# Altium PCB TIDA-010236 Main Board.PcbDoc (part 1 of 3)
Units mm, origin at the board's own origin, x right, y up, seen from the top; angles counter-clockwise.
Board outline 180 x 120 mm, 2 copper layers (Top Layer, Bottom Layer), stack 1.571 mm thick; 265 components, 145 nets, 704 pads, 547 vias.
Unrouted connection lines stored in the file: 155.
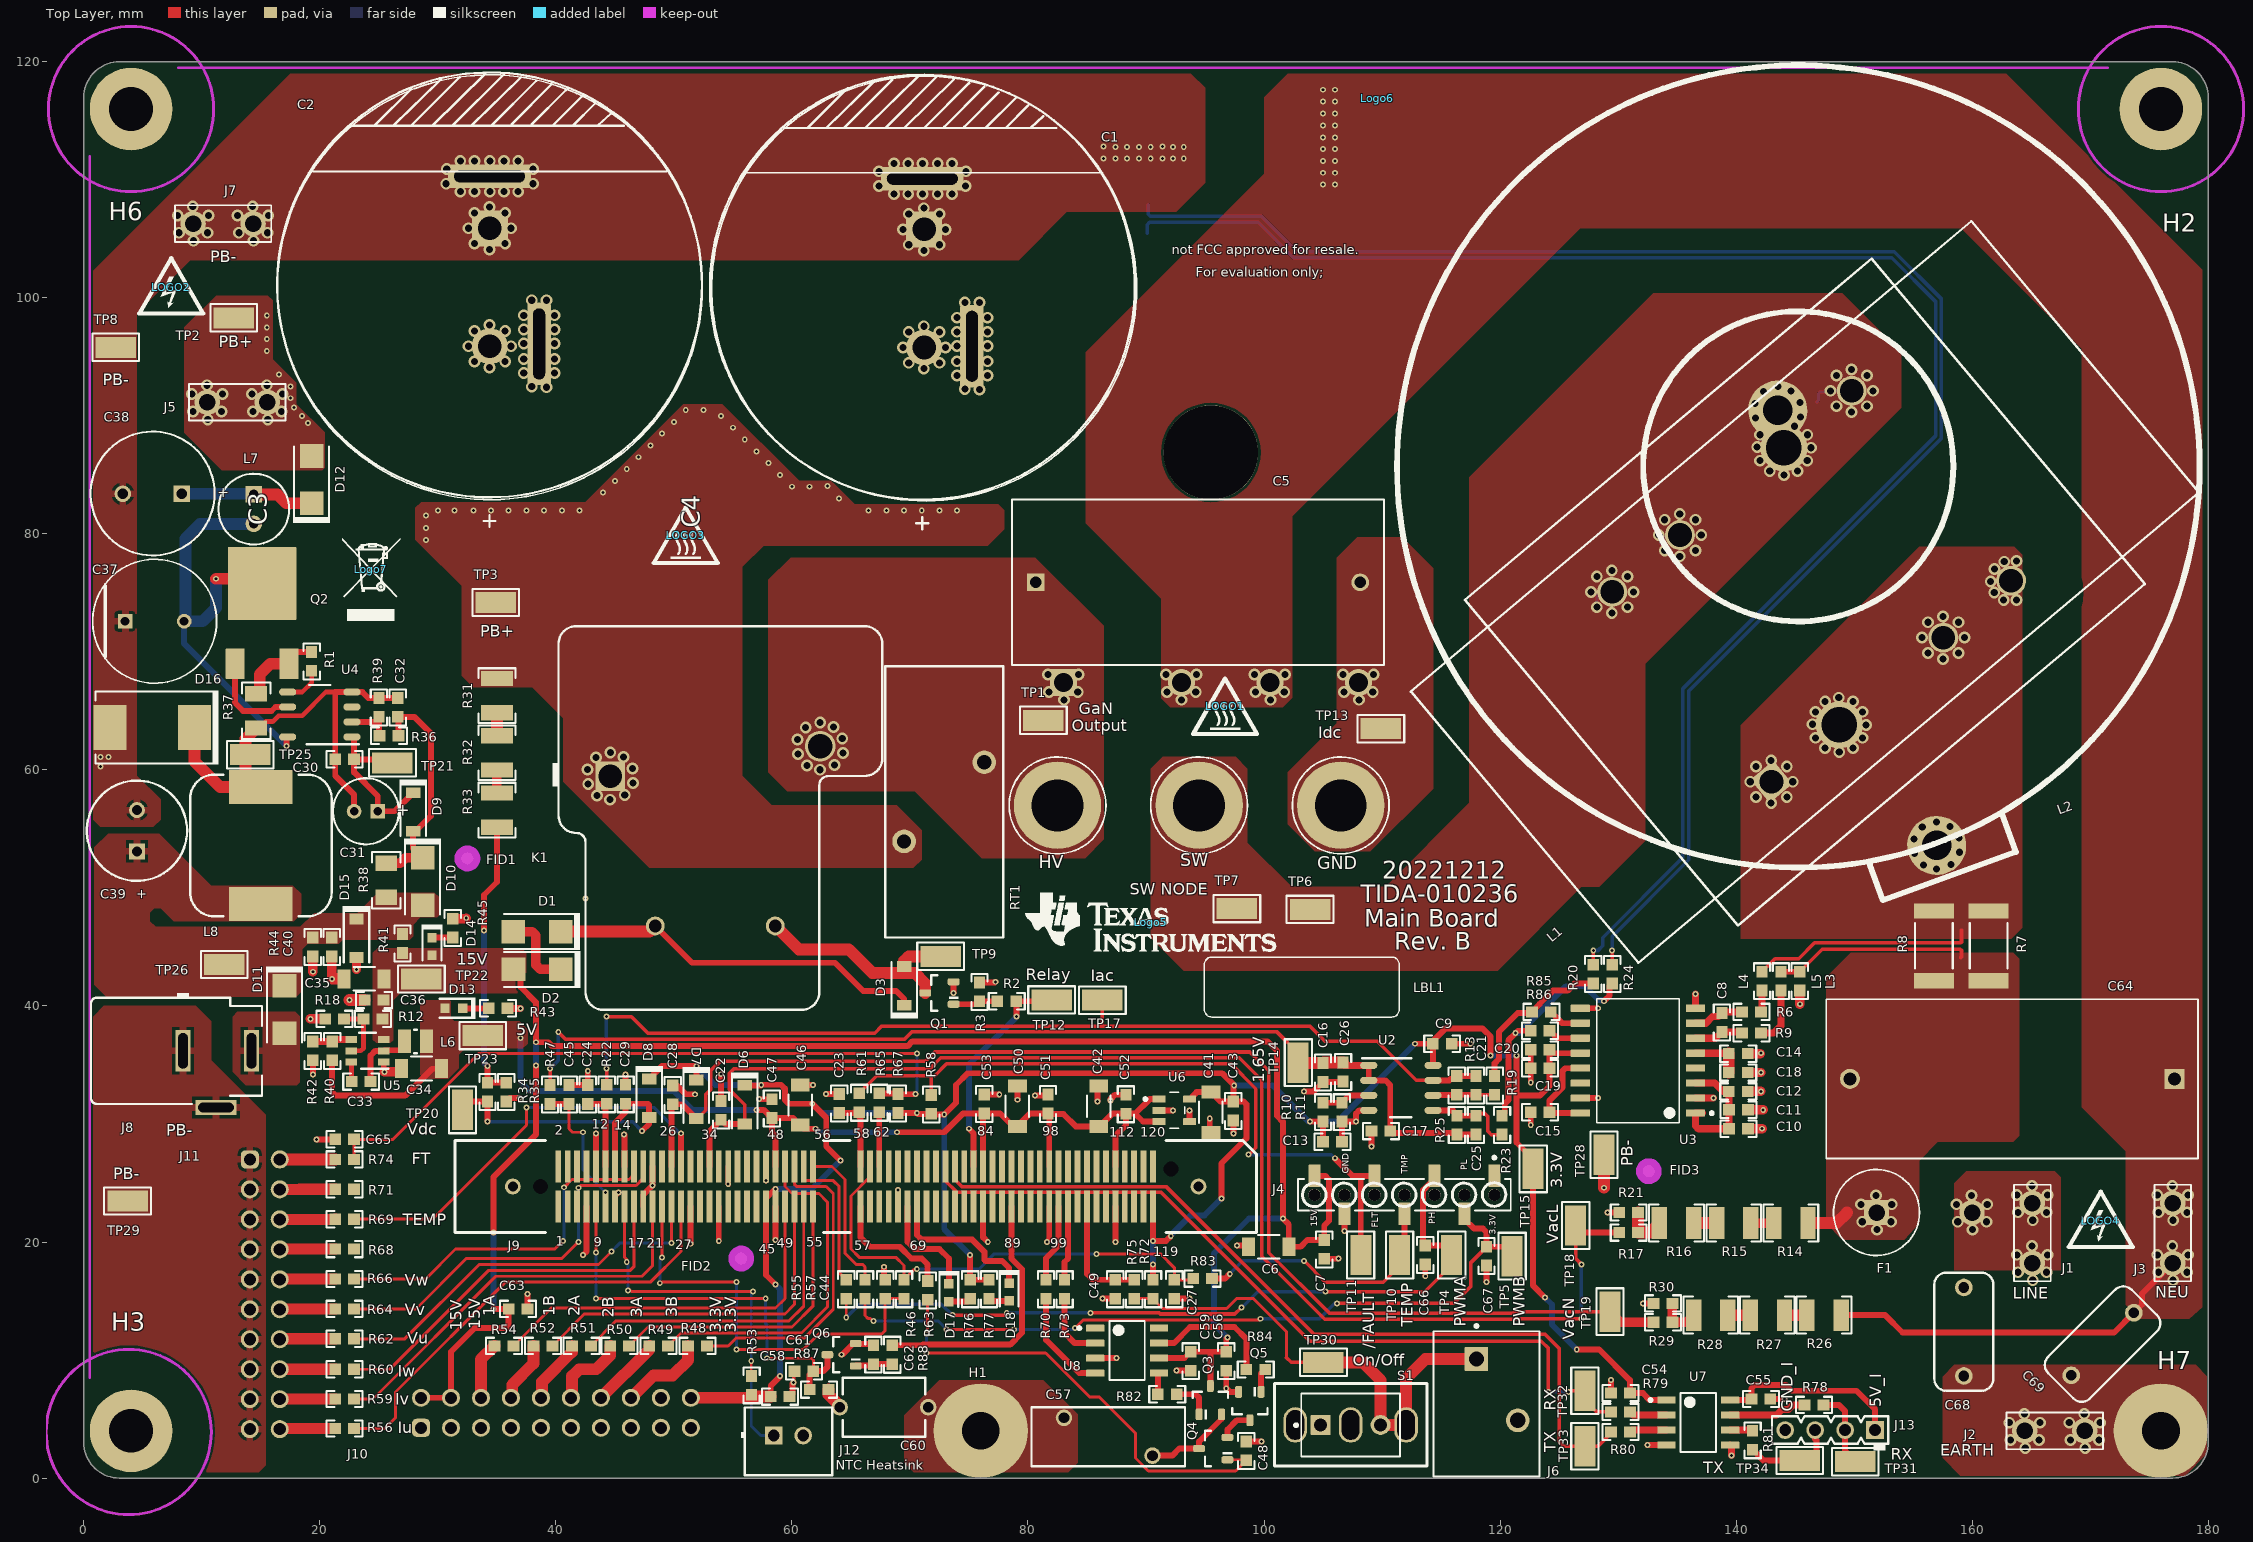
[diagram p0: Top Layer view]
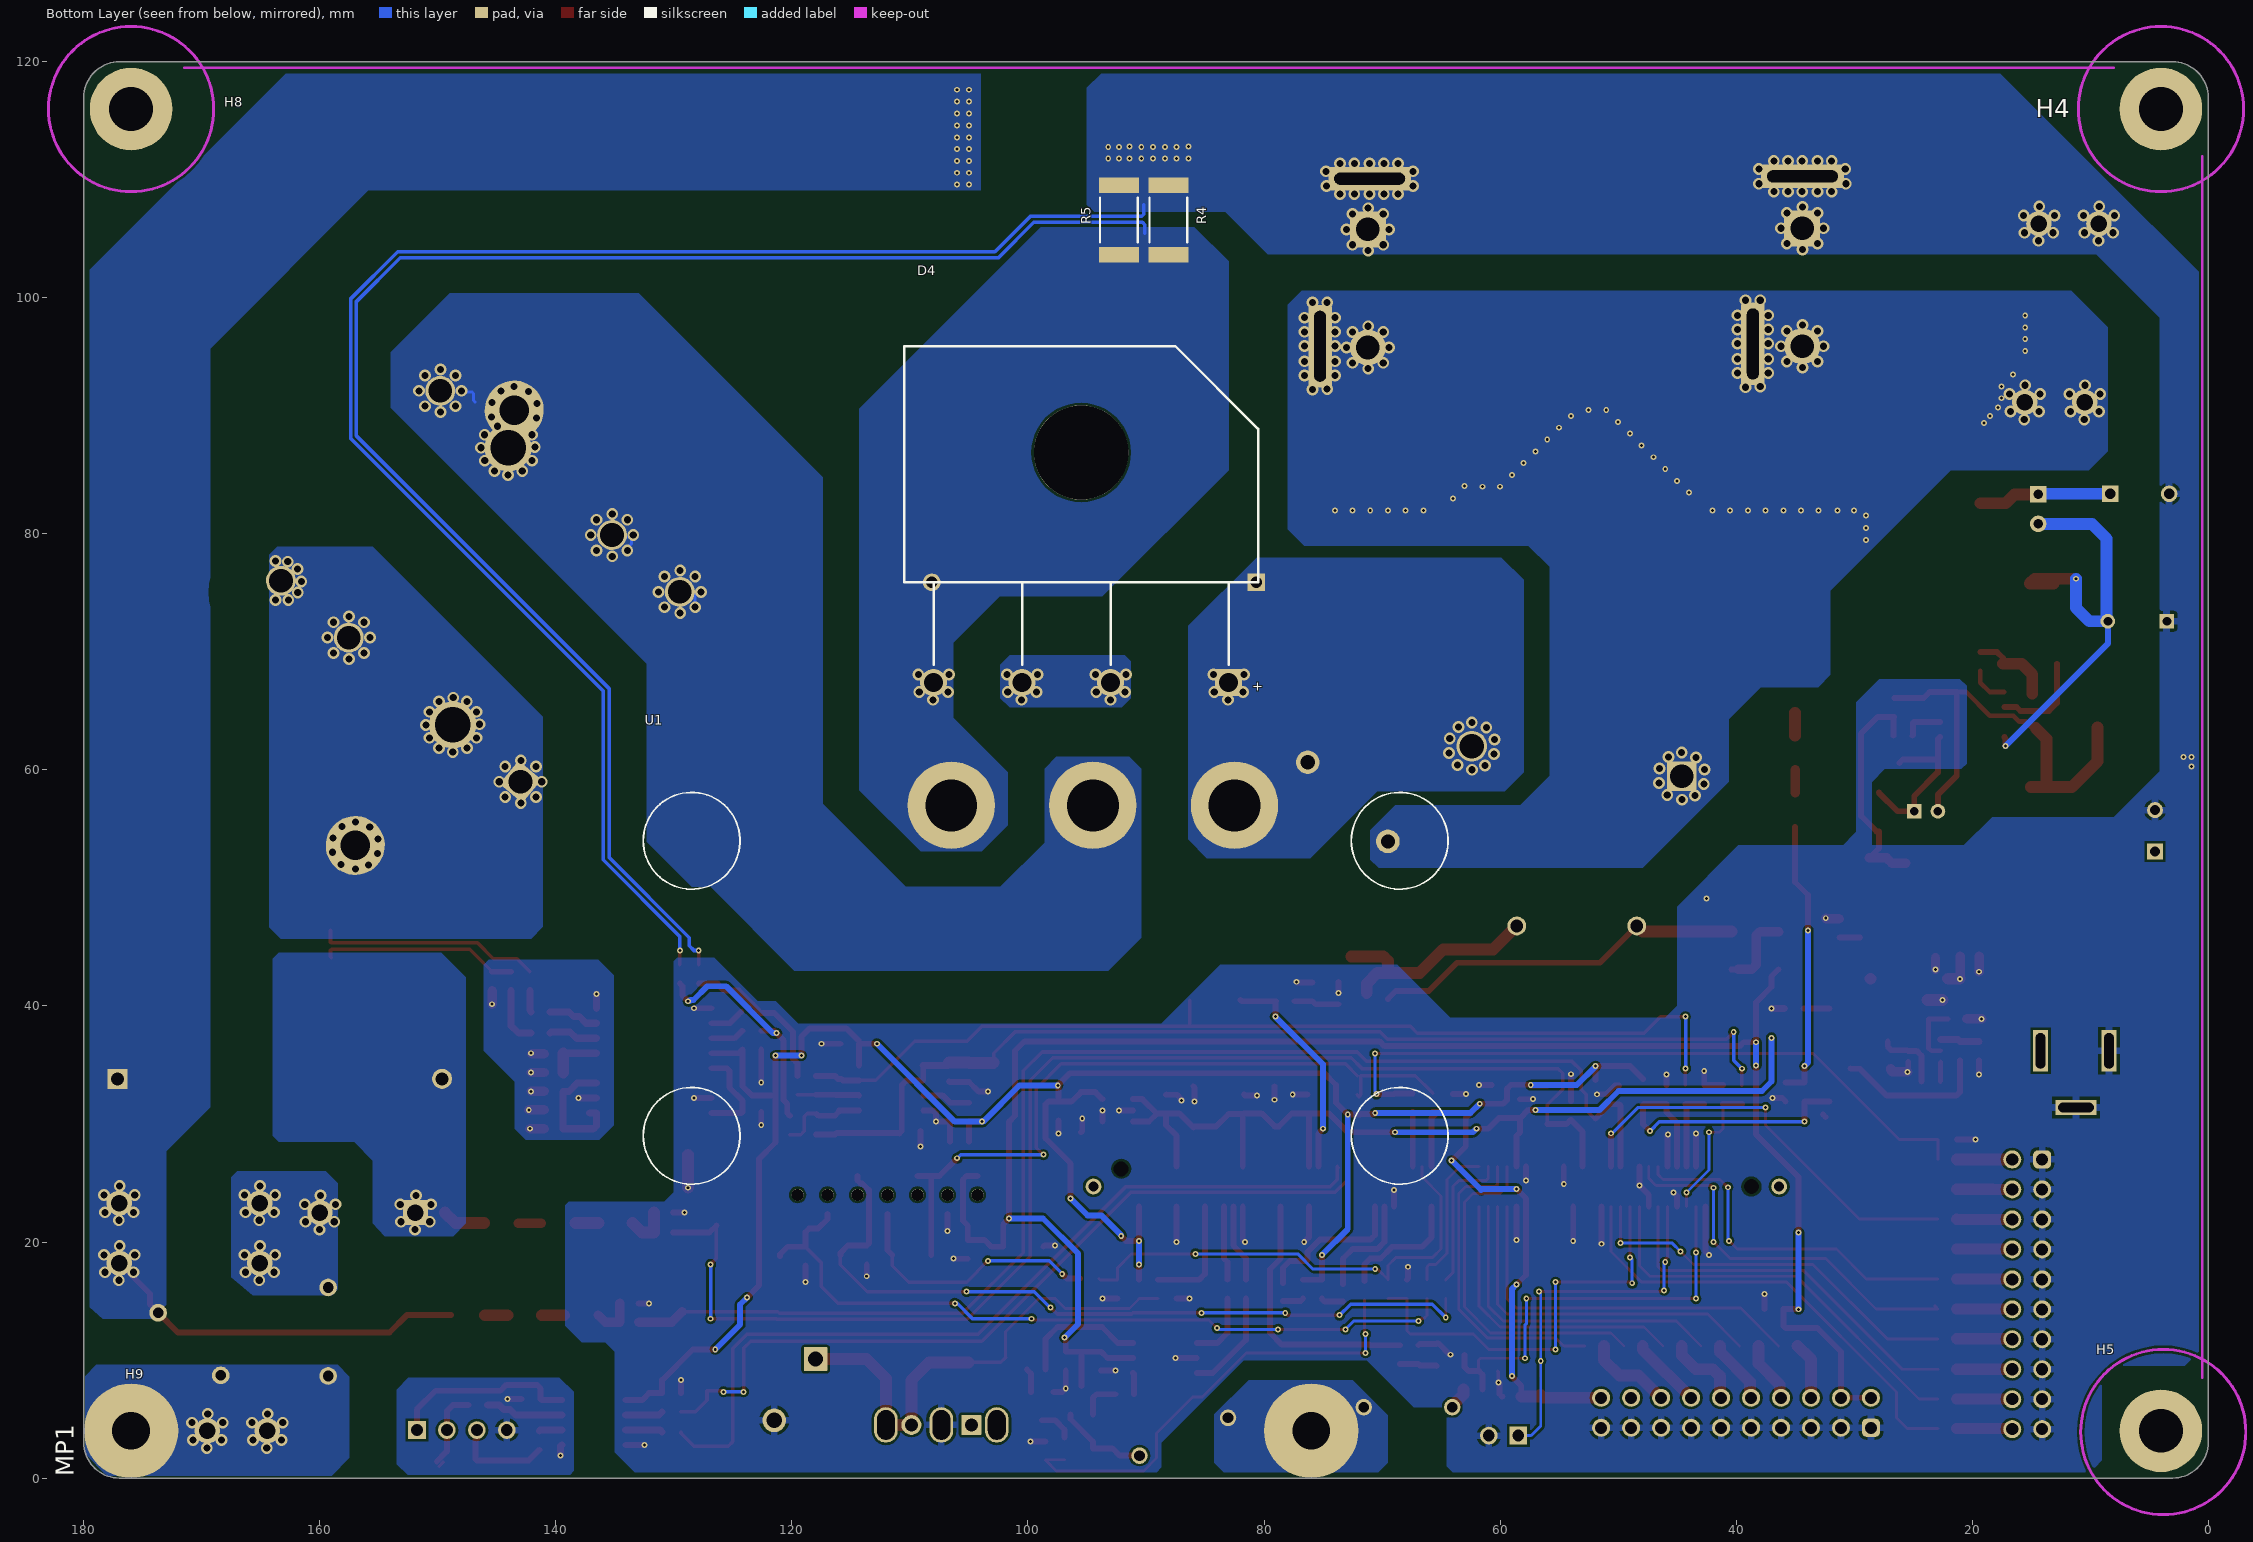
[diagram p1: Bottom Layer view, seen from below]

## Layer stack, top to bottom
Top Solder: solder mask 0.0102, Solder Resist, Dk 3.5
Top Layer: signal copper 0.0356
Dielectric 1: core 1.5, FR-4, Dk 4.2
Bottom Layer: signal copper 0.0356
Bottom Solder: solder mask 0.0102, Solder Resist, Dk 3.5

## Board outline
177,120 cw(c177,117) 180,117 180,3 cw(c177,3) 177,0 3,0 cw(c3,3) 0,3 0,117 cw(c3,117) 3,120

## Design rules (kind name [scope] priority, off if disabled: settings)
Clearance PB-ToACN [InNetClass('GND_NetClass') vs InNetClass('ACN_NetClass')] p1: gap=3 ignorepadtopadclearanceinfootprint=TRUE
Clearance ISOToAll [InNetClass('ISO_NetClass') vs Not (ISO_NetClass)] p2: gap=6.3 ignorepadtopadclearanceinfootprint=TRUE
Clearance PB-ToACL [InNetClass('GND_NetClass') vs InNetClass('ACL_NetClass')] p3: gap=2 ignorepadtopadclearanceinfootprint=TRUE
Clearance PB+ToACN [InNetClass('PB+_NetClass') vs InNetClass('ACN_NetClass')] p4: gap=3 ignorepadtopadclearanceinfootprint=FALSE
Clearance PB+ToACL [InNetClass('PB+_NetClass') vs InNetClass('ACL_NetClass')] p5: gap=3 ignorepadtopadclearanceinfootprint=TRUE
Clearance PB+ToPB- [InNetClass('PB+_NetClass') vs InNetClass('GND_NetClass')] p6: gap=1 ignorepadtopadclearanceinfootprint=TRUE
Clearance ACLToACN [InNetClass('ACL_NetClass') vs InNetClass('ACN_NetClass')] p7: gap=5 ignorepadtopadclearanceinfootprint=TRUE
Clearance SMTPadToTHHole [OnLayer('Multi-Layer') vs OnLayer('Bottom Paste')] p8: gap=0.35 ignorepadtopadclearanceinfootprint=FALSE except(0: Arc-Hole Track-Hole SMDPad-Hole THPad-Hole Via-Hole Fill-Hole Poly-Hole Region-Hole Text-Hole; 3: SMDPad-THPad)
Clearance [All] p9: gap=0.2 ignorepadtopadclearanceinfootprint=FALSE
ComponentClearance [All] p1 off: gap=0.254 collisioncheckmode=3 verticalgap=0.254 showdistances=FALSE
DiffPairsRouting DiffPair_CurrentDiffPairsRouting [InDifferentialPair('I')] p1: maxlimit=0.4 minlimit=0.2 mostfreqgap=0.25 toplayer_minwidth=0.2 toplayer_maxwidth=0.4 toplayer_prefwidth=0.25 bottomlayer_minwidth=0.2 bottomlayer_maxwidth=0.4 bottomlayer_prefwidth=0.25 maxuncoupledlength=12.7
FabricationTestPointUsage TestPointUsage [InNet('+5V')] p1: valid=0 allowmultiple=FALSE
FabricationTestpoint Testpoint [InNet('+5V')] p1: side=2 testpointundercomponent=TRUE minsize=0.4 maxsize=1 preferedsize=0.4 minholesize=0 maxholesize=1.016 preferedholesize=0.813 testpointgrid=0.025 allowsidebottom=TRUE usegrid=TRUE gridtolerance=0
Height [All] p1: minheight=0 maxheight=100 prefheight=12.7
HoleSize [All] p1: absolutevalues=TRUE maxlimit=10 minlimit=0.025 maxpercent=80.000 minpercent=20.000
MatchedLengths DiffPair_CurrentMatchedLengths [InDifferentialPair ('C')] p1: tolerance=25.4 checknetsindiffpair=FALSE checkdiffpairvsdiffpair=TRUE checkxsignals=TRUE checkothers=TRUE
MinimumSolderMaskSliver [All vs not InComponent('J9')] p1: minsoldermaskwidth=0.14
PlaneConnect [All] p1: planeconnectstyle=Direct reliefexpansion=0.508 reliefentries=4 reliefconductorwidth=0.254 reliefairgap=0.254
PolygonConnect Polygon_Direct [InComponent('U1') or InNet('NetD4_2')  or   InNet('EARTH')   OR InNet('EARTH1') or  InNet('LINE_Filtered')   or  InNet('LINE_Filtered1')   or  InNet('NEU_Filtered')   or  InNet('PBGan')    or  InNet('Idc') or  InNet('PB+')  or InComponent('L2')  or InComponent('C1') or InComponent('C2') or InComponent('C3')    or InComponent('C4')        or InComponent('J7')    or InComponent('L1')      or InComponent('F1')] p1: connectstyle=Direct reliefconductorwidth=0.254 reliefentries=4 polygonreliefangle="90 Angle" airgapwidth=0.254
PolygonConnect [All] p2: thpad.connectstyle=Relief thpad.reliefconductorwidth=0.6 thpad.reliefentries=4 thpad.polygonreliefangle="90 Angle" thpad.airgapwidth=0.254 smdpad.connectstyle=Direct smdpad.reliefconductorwidth=0.254 smdpad.reliefentries=4 smdpad.polygonreliefangle="90 Angle" smdpad.airgapwidth=0.254 via.connectstyle=Direct via.reliefconductorwidth=0.254 via.reliefentries=4 via.polygonreliefangle="90 Angle" via.airgapwidth=0.254
RoutingVias [All] p1: holewidth=0.25 width=0.5 viastyle="Through Hole" minholewidth=0.2 minwidth=0.4 maxholewidth=0.8 maxwidth=1.27
SilkToSilkClearance [All] p1 off: silktosilkclearance=0.254
SilkToSolderMaskClearance SilkscreenOverComponentPads [IsPad] p1 off: minsilkscreentomaskgap=0.254 clearancetoexposedcopper=TRUE
SolderMaskExpansion [All] p1: expansion=0.102 istentingtop=FALSE
Width [All] p1: maxlimit=6 minlimit=0.2 preferedwidth=0.25 minimp=50.000000 maximp=50.000000 favimp=50.000000
20 further rules are at their usual default settings.

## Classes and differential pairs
net class ACN_NetClass: NEU_Filtered
component class U_ACTIVE_EMI: C56 C57 C59 C60 C61 C62 Q3 Q4 Q5 Q6 Q7 Q8 R82 R84 R87 R88 U8
net class ISO_NetClass: 5V_ISO GND_ISO NetR78_2 NetR81_1 UART_RX UART_TX
net class ACL_NetClass: LINE_Filtered LINE_Filtered1 NetC8_1 NetC8_2 NetC10_1 NetC10_2 NetC14_2 NetL1_1 NetL4_1 NetL5_1 NetU5_4
net class PB+_NetClass: NetC30_1 NetC30_2 NetC32_1 NetC37_2 NetC38_1 NetQ2_1 NetQ2_3 NetR1_2 NetR36_1 PB+ PBGaN SWNODE1
net class GND_NetClass: 3V3 5V 15V /FAULT ACTIVE_EMI_RESET ACTIVE_EMI_SENSE ANA_Iac ANA_VacL ANA_VacN ANA_Vdc GaN_TEMP Heatsink_Temp Idc INJ_PD_LEVEL INJ_PD_PULSE INJ_PU_PULSE INRUSH_CTRL IPM_Temp Iu Iv Iw LED_GREEN LED_RED MCU1V2 Motor_Fault NetC15_1 NetC21_1 NetC21_2 NetC23_2 NetC25_1 NetC33_1 NetC33_2 NetC39_1 NetC49_1 NetD1_1 NetD1_2 NetD3_2 NetD11_2 NetD13_2 NetD14_2 NetD17_1 NetD18_1 NetJ2_1 NetJ2_2 NetJ2_4 NetJ2_13 NetJ2_16 NetJ2_21 NetJ2_27 NetJ2_29 NetJ2_31 NetJ2_32 NetJ2_37 NetJ2_39 NetJ2_40 NetJ2_42 NetJ2_44 NetJ2_45 NetJ2_59 NetJ2_61 NetJ2_63 NetJ2_64 NetJ2_66 NetJ2_68 NetJ2_70 NetJ2_72 NetJ2_74 NetJ2_77 NetJ2_79 NetJ2_81 NetJ2_85 NetJ2_86 NetJ2_87 NetJ2_88 NetJ2_89 NetJ2_90 NetJ2_91 NetJ2_92 NetJ2_93 NetJ2_94 NetJ2_95 NetJ2_96 NetJ2_99 NetJ2_100 NetJ2_101 NetJ2_102 NetJ2_103 NetJ2_104 NetJ2_106 NetJ2_107 NetJ2_108 NetJ2_109 NetJ2_110 NetJ2_113 NetJ2_114 NetJ2_115 NetJ2_116 NetJ2_117 NetJ2_118 NetJ2_119 NetJ2_120 NetJ9_54 NetJ9_56 NetJ9_57 NetJ9_62 NetJ9_99 NetJ9_101 NetJ10_6 NetJ10_8 NetJ10_10 NetJ10_12 NetJ10_14 NetJ10_16 NetJ11_2 NetJ11_4 NetJ11_6 NetJ11_8 NetJ11_10 NetJ11_12 NetJ11_14 NetJ11_16 NetJ11_18 NetJ11_20 NetQ1_1 NetR10_1 NetR12_1 NetR15_2 NetR16_2 NetR19_1 NetR23_1 NetR27_2 NetR28_2 NetR32_2 NetR33_2 NetR40_1 NetR79_2 NetR80_1 NetR85_2 NetR86_2 On/Off PB- PWM_1A PWM_1B PWM_2A PWM_2B PWM_3A PWM_3B PWM_4A PWM_4B REF1V65 REF1V65_AD TCK TDI TDO TEMP_L TEMP_L_Filter TMS UART_RX_MCU UART_TX_MCU Vu Vv Vw
net class HV: NetC30_2 NetC38_1 NetQ2_3 PB+
component class PowerStage: C1 C2 C3 C4 C5 C6 C7 C8 C9 C10 C11 C12 C13 C14 C15 C16 C17 C18 C19 C20 C21 C22 C24 C25 C26 C28 C29 C64 C66 C67 C68 C69 D1 D2 D3 D4 D6 D7 D8 F1 J4 K1 L1 L2 L3 L4 L5 Q1 R2 R3 R4 R5 R6 R7 R8 R9 R10 R11 R13 R14 R15 R16 R17 R19 R20 R21 R22 R23 R24 R25 R26 R27 R28 R29 R30 R31 R32 R33 R34 R35 R85 R86 RT1 TP1 TP2 TP3 TP4 TP5 TP6 TP7 TP8 TP9 TP10 TP11 TP12 TP13 TP14 TP17 TP18 TP19 TP20 U1 U2 U3
component class "Mounting Holes": H1 H7
component class Logo: Logo5
component class Label: LBL1
component class Header: J13
component class FiducialMark: FID1 FID2 FID3
component class Main: J1 J2 J3 J5 J6 J7 J13 S1
component class ControlStage: C23 C27 C44 C45 C46 C47 C48 C49 C50 C51 C52 C53 C54 C55 C58 C63 C65 D17 D18 DC1 J9 J10 J11 J12 R46 R47 R48 R49 R50 R51 R52 R53 R54 R55 R56 R57 R58 R59 R60 R61 R62 R63 R64 R65 R66 R67 R68 R69 R70 R71 R72 R73 R74 R75 R76 R77 R78 R79 R80 R81 R83 TP30 TP31 TP32 TP33 TP34 U7
component class AuxP: !PCB1 C30 C31 C32 C33 C34 C35 C36 C37 C38 C39 C40 C41 C42 C43 D9 D10 D11 D12 D13 D14 D15 D16 FID1 FID2 FID3 H1 H2 H3 H4 H5 H6 H7 H8 H9 J8 L6 L7 L8 LBL1 LOGO1 LOGO2 LOGO3 LOGO4 Logo5 Logo6 Logo7 Q2 R1 R12 R18 R36 R37 R38 R39 R40 R41 R42 R43 R44 R45 TP15 TP21 TP22 TP23 TP25 TP26 TP28 TP29 U4 U5 U6

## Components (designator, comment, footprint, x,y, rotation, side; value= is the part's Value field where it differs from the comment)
C1 "S861021486045" FP-S861021486045_RADIAL-MFG 71.2,100.8 r270 top locked value=1mF
C2 "S861021486045" FP-S861021486045_RADIAL-MFG 34.4,100.9 r270 top locked value=1mF
C3 "820uF" "Cap_35x60mm_Snap in" 34.375,101.1 r90 top
C4 "820uF" "Cap_35x60mm_Snap in" 71.05,100.9 r90 top
C5 "ECWFG2J225" B32924_24.5mm 94.4,75.9 r0 top value=2.2uF
C6 "GRM31CR71E106KA12L" 1206_180 100.4,19.6 r180 top value=10uF
C7 "GRM188R71E104KA01D" 0603#1 105.1,19.38 r270 top value=0.1uF
C8 "GRM188R71H103KA01D" 0603#1 138.8,38.6 r270 top value=0.01uF
C9 "GRM188R71E104KA01D" 0603#1 115.1,36.8 r0 top value=0.1uF
C10 "GRJ188R71E105KE11D" 0603#1 140.2,29.6 r0 top value=1uF
C11 "GCJ188R71H102KA01D" 0603#1 140.2,31.2 r0 top value=1000pF
C12 "GRM188R71E104KA01D" 0603#1 140.186,32.762 r180 top value=0.1uF
C13 "GRM188R71E104KA01D" 0603#1 105.8,28.5 r0 top value=0.1uF
C14 "GCJ188R71H102KA01D" 0603#1 140.186,35.962 r180 top value=1000pF
C15 "GRM188R71E104KA01D" 0603#1 123.4,31 r180 top value=0.1uF
C16 "GRJ188R71E105KE11D" 0603#1 105,34.361 r270 top value=1uF
C17 "GRM188R71E104KA01D" 0603#1 109.9,29.4 r180 top value=0.1uF
C18 "GRM188R71E104KA01D" 0603#1 140.186,34.361 r180 top value=0.1uF
C19 "GRJ188R71E105KE11D" 0603#1 123.4,34.727 r180 top value=1uF
C20 "GCJ188R71H102KA01D" 0603#1 123.4,36.3 r0 top value=1000pF
C21 "GRM1885C1H221JA01D" 0603#1 117.953,33.275 r270 top value=220pF
C22 "GRM188R71H103KA01D" 0603#1 54,31.156 r90 top value=0.01uF
C23 "GRM188R71H222KA01D" 0603#1 64,31.74 r270 top value=2200pF
C24 "GRM188R71H473KA61D" 0603#1 42.7,32.5 r90 top value=0.047uF
C25 "GRM1885C1H221JA01D" 0603#1 117.953,29.9 r270 top value=220pF
C26 "GRM188R71E104KA01D" 0603#1 106.7,34.4 r270 top value=0.1uF
C27 "GRM188R71H103KA01D" 0603#1 92.4,16 r270 top value=0.01uF
C28 "GRM188R71H103KA01D" 0603#1 49.9,32.475 r90 top value=0.01uF
C29 "GRM188R72A332KA01D" 0603#1 45.9,32.517 r90 top value=3300pF
C30 "GRM188R71E104KA01D" 0603#1 22.1,60.9 r180 top value=0.1uF
C31 "UPW1V100MDD6" PW_500x700 23.9,56.5 r180 top value=10uF
C32 "GRM1885C1H220JA01D" 0603#1 26.6,65.3 r90 top value=22pF
C33 "GRM188R71E104KA01D" 0603#1 23.5,33.595 r180 top value=0.1uF
C34 "GRM31CR71E106KA12L" 1206_180 28.6,34.701 r180 top value=10uF
C35 "GRM31CR71E106KA12L" 1206_180 23.75,42.3 r180 top value=10uF
C36 "GRM188R71E104KA01D" 0603#1 24.6,40.5 r180 top value=0.1uF
C37 "UCY2W150MPD1TD" FP-UCY2W150MPD1TD_RADIAL-MFG 6,72.6 r0 top value=15µF
C38 "UVY2W4R7MPD1TD" UVY_1000x1250 5.8,83.4 r180 top value=4.7uF
C39 "UHV1E391MPD" HV_800x1500 4.5,54.85 r90 top value=390uF
C40 "GRM188R71E104KA01D" 0603#1 21,45 r270 top value=0.1uF
C41 "GRM31CR71E106KA12L" 1206_180 95.5,31 r270 top value=10uF
C42 "GRM31CR71E106KA12L" 1206_180 86,31.5 r90 top value=10uF
C43 "GRM188R71E104KA01D" 0603#1 97.4,31.1 r270 top value=0.1uF
C44 "GRJ188R71E105KE11D" 0603#1 67.9,16 r90 top value=1uF
C45 "GRM188R71E104KA01D" 0603#1 41.1,32.5 r90 top value=0.1uF
C46 "GRM31CR71E106KA12L" 1206_180 60.7,31.6 r270 top value=10uF
C47 "GRM188R71E104KA01D" 0603#1 58.3,31.3 r270 top value=0.1uF
C48 "GRJ188R71E105KE11D" 0603#1 98.5,2.3 r90 top value=1uF
C49 "GRM188R71E104KA01D" 0603#1 87.4,16 r270 top value=0.1uF
C50 "GRM31CR71E106KA12L" 1206_180 79.1,31.5 r90 top value=10uF
C51 "GRM188R71E104KA01D" 0603#1 81.7,31.7 r90 top value=0.1uF
C52 "GRM188R71E104KA01D" 0603#1 88.3,31.675 r90 top value=0.1uF
C53 "GRM188R71E104KA01D" 0603#1 76.3,31.7 r90 top value=0.1uF
C54 "GRJ188R71E105KE11D" 0603#1 130.2,7.2 r180 top value=1uF
C55 "GRJ188R71E105KE11D" 0603#1 142.1,6.7 r0 top value=1uF
C56 "GRJ188R71E105KE11D" 0603#1 96.8,9.9 r270 top value=1uF
C57 "AY2472M49Y5US63L7" AY2_1300x500_Straight 86.8,3.5 r180 top value=4700pF
C58 "GRJ188R71E105KE11D" 0603#1 59,6.901 r0 top value=1uF
C59 "GRJ188R71E105KE11D" 0603#1 93.8,9.9 r270 top value=1uF
C60 "DE2B3KY101KN3AU02F" KY_700x500x1000 67.8,6 r180 top value=100pF
C61 "GRM1885C1H151JA01D" 0603#1 61.007,9.055 r180 top value=150pF
C62 "GRM1885C1H220JA01D" 0603#1 66.905,10.45 r90 top value=22pF
C63 "GRJ188R71E105KE11D" 0603#1 36.8,14.333 r0 top value=1uF
C64 "890334027012CS" FP-890334027012CS_RADIAL-MFG 163.4,33.825 r180 top value=1.2µF
C65 "GCJ188R71H102KA01D" 0603#1 22.1,28.7 r0 top value=1000pF
C66 "C0603C101J5GACTU" 0603#1 113.665,18.9 r90 top value=100pF
C67 "C0603C101J5GACTU" 0603#1 118.85,18.8 r90 top value=100pF
C68 "DE2E3KY472MB3BM02F" KY_1000x500x1300 159.3,12.4 r270 top value=4700pF
C69 "DE2E3KY472MB3BM02F" KY_1000x500x1300 171.052,11.352 r45 top value=4700pF
D1 "S1MTR" SMA 38.4,46.3 r180 top value=1000V
D2 "S1MTR" SMA 38.407,43.1 r180 top value=1000V
D3 "BAT54T1G" SOD-123 69.5,41.7 r90 top value=30V
D4 "Diode bridge 600VDC 25A GBJ" DIODE_BRIDGE_HORIZONTAL_GBJ 83,67.4 r180 bottom locked value=600V
D6 "BAT54T1G" SOD-123 56,31.637 r270 top value=30V
D7 "BAT54T1G" SOD-123 51.9,32.1 r270 top value=30V
D8 "BAT54T1G" SOD-123 47.9,32.187 r270 top value=30V
D9 "1N4148W-7-F" SOD-123 27.9,56.437 r270 top value=100V
D10 "ES1JTR" SMA 28.7,50.55 r270 top value=600V
D11 "S1MTR" SMA 17,39.7 r270 top value=1000V
D12 "S1MTR" SMA 19.3,84.6 r90 top value=1000V
D13 "LTST-C193KGKT-5A" LTST-C193_Green 31.35,39.8 r0 top value=Green
D14 "LTST-C193KRKT-5A" LTST-C193_Red 29.5,45.05 r90 top value=Red
D15 "CRZ18" SOD-123 23.1,45.738 r270 top value=18V
D16 "MURS360T3G" SMC 5.8,63.6 r180 top value=600V
D17 "LTST-C193KGKT-5A" LTST-C193_Green 73.3,15.7 r90 top value=Green
D18 "LTST-C193KRKT-5A" LTST-C193_Red 78.4,15.76 r90 top value=Red
F1 "0524025" FP-0525025.MXEP_vm_AXIAL-MFG 151.9,22.5 r0 top
FID1 "Fiducial" Fiducial10-20 32.5,52.5 r270 top
FID2 "Fiducial" Fiducial10-20 55.7,18.6 r270 top
FID3 "Fiducial" Fiducial10-20 132.6,26 r270 top
H1 "NY PMS 440 0025 PH" "NY PMS 440 0025 PH" 76,4 r180 top
H2 "29311" Keystone29311 176,116 r180 top
H3 "29311" Keystone29311 4,4 r180 top
H4 "971120321" Wurth_971120321 4,116 r0 bottom
H5 "971120321" Wurth_971120321 4,4 r0 bottom
H6 "29311" Keystone29311 4,116 r180 top
H7 "NY PMS 440 0025 PH" "NY PMS 440 0025 PH" 176,4 r180 top
H8 "971120321" Wurth_971120321 176,116 r0 bottom
H9 "971120321" Wurth_971120321 176,4 r0 bottom
J1 "63824-1" FP-63824-1_CONN_7MM92_3MM11-MFG 165.1,20.76 r270 top
J2 "63824-1" FP-63824-1_CONN_7MM92_3MM11-MFG 167,4 r180 top
J3 "63824-1" FP-63824-1_CONN_7MM92_3MM11-MFG 177,20.76 r90 top
J4 "SSM-107-L-SV-BE" FP-SSM-107-L-SV-BE_HDR7-MFG 111.9,24 r180 top
J5 "63824-1" FP-63824-1_CONN_7MM92_3MM11-MFG 13,91.157 r180 top
J6 "1-2834011-2" FP-1-2834011-2_HDR2-MFG 118.85,6.285 r0 top
J7 "63824-1" FP-63824-1_CONN_7MM92_3MM11-MFG 11.8,106.3 r180 top
J8 "694106301002" Wurth_694106301002 11.3,36.2 r90 top
J9 "HSEC8-160-01-L-DV-A-BL" controlCARD-120HSEC 63.557,24.678 r0 top locked
J10 "TSS-110-02-G-D" Samtec_TSS-110-02-G-D 40,5.53 r90 top
J11 "TSS-110-02-G-D" Samtec_TSS-110-02-G-D 15.33,15.57 r0 top
J12 "B2B-XH-A(LF)(SN)" JST_B2B-XH-A 59.7,3.6 r0 top
J13 "3-644695-4" TE_644695-4 147.97,4.065 r180 top
K1 "T9AS1D12-15" Relay_T9AS1D12 53.5,54.4 r0 top locked
L1 "1" BOOST_INDUCTOR_250UH 143,59 r40 top
L2 "ARLDC807842C201N1B" ARLDC807842C201N1B 157,53.5 r200 top locked value=300uH
L3 "782631182" 0603#1 145.4,42.1 r90 top value="1800 ohm"
L4 "782631182" 0603#1 142.2,42.1 r90 top value="1800 ohm"
L5 "782631182" 0603#1 143.8,42.1 r90 top value="1800 ohm"
L6 "74404024100" WE_LQS_252012 28.1,37 r0 top value=10uH
L7 "7447462102" WE-TI_5075 14.4,82.1 r270 top value=1mH
L8 "744770147" WE-PD_1280 15,53.6 r270 top value=47uH
LBL1 "THT-14-423-10" Label_650x200 103.2,41.6 r0 top
LOGO1 "CAUTION HOT SURFACE" IEC_HotSurface_Small 96.7,65.4 r0 top
LOGO2 "DANGER HIGH VOLTAGE" IEC_HighVoltage_Small 7.4,100.9 r0 top
LOGO3 "CAUTION HOT SURFACE" IEC_HotSurface_Small 51,79.9 r0 top
LOGO4 "DANGER HIGH VOLTAGE" IEC_HighVoltage_Small 170.903,21.8 r0 top
Logo5 "Texas Instruments" TI_Stacked_Overlay_Small 90.4,47.099 r0 top
Logo6 "FCC disclaimer" FCC_disclaimer_stacked 109.6,116.9 r180 top
Logo7 "WEEE logo" WEEE_Minimum 24.3,77 r0 top
MP1 "TIDA-010236 Main Heatsink" 0-MFG 90,60 r0 bottom
Q1 "2V7002KT1G" SOT-23 72.5,41.1 r180 top value=60V
Q2 "AOD4S60" DPAK 15.1,72.4 r90 top value=600V
Q3 "2V7002KT1G" SOT-23 95.45,6.6 r90 top value=60V
Q4 "2V7002KT1G" SOT-23 95.7,2.5 r180 top value=60V
Q5 "2V7002KT1G" SOT-23 98.8,6.1 r270 top value=60V
Q6 "2V7002KT1G" SOT-23 64.2,10.45 r180 top value=60V
R1 "RC0603FR-07300RL" 0603#1 19.3,69.2 r270 top value=300
R2 "RC0603FR-07100RL" 0603#1 78.2,40.4 r0 top value=100
R3 "RC0603FR-0710KL" 0603#1 75.893,41.2 r270 top value=10.0k
R4 "ERJ-M1WTF2M0U" 2512 88.1,106.6 r90 bottom value=0.002
R5 "ERJ-M1WTF2M0U" 2512 92.3,106.6 r90 bottom value=0.002
R6 "RC0603FR-0710RL" 0603#1 141.3,39.5 r180 top value=10.0
R7 "ERJ-M1WTF2M0U" 2512 156.758,45.1 r90 top value=0.002
R8 "ERJ-M1WTF2M0U" 2512 161.4,45.1 r90 top value=0.002
R9 "RC0603FR-0710RL" 0603#1 141.3,37.7 r180 top value=10.0
R10 "RC0603FR-0710KL" 0603#1 105,31 r270 top value=10.0k
R11 "RC0603FR-0710KL" 0603#1 106.6,31 r90 top value=10.0k
R12 "RC0603FR-0751K1L" 0603#1 24.5,38.9 r0 top value=51.1k
R13 "RC0603FR-072K4L" 0603#1 116.325,33.275 r270 top value=2.40k
R14 "RC1210FR-07330KL" 1210 144.65,21.6 r180 top value=330k
R15 "RC1210FR-07330KL" 1210 139.8,21.6 r180 top value=330k
R16 "RC1210FR-07330KL" 1210 134.95,21.6 r180 top value=330k
R17 "RC0603FR-07100RL" 0603#1 130.9,20.8 r180 top value=100
R18 "RC0603FR-075K1L" 0603#1 21.25,38.9 r0 top value=5.10k
R19 "RC0603FR-073K3L" 0603#1 119.541,33.275 r270 top value=3.30k
R20 "RC0603JR-070RL" 0603#1 127.9,42.7 r270 top value=0
R21 "RC0603FR-075K1L" 0603#1 130.9,22.5 r0 top value=5.10k
R22 "RC0603FR-07100RL" 0603#1 44.3,32.517 r270 top value=100
R23 "RC0603FR-073K3L" 0603#1 120.175,29.9 r270 top value=3.30k
R24 "RC0603JR-070RL" 0603#1 129.5,42.7 r270 top value=0
R25 "RC0603FR-072K4L" 0603#1 116.35,29.9 r90 top value=2.40k
R26 "RC1210FR-07330KL" 1210 147.45,13.8 r180 top value=330k
R27 "RC1210FR-07330KL" 1210 142.65,13.8 r180 top value=330k
R28 "RC1210FR-07330KL" 1210 137.85,13.8 r180 top value=330k
R29 "RC0603FR-07100RL" 0603#1 133.8,13.2 r180 top value=100
R30 "RC0603FR-075K1L" 0603#1 133.8,14.8 r0 top value=5.10k
R31 "RC1210FR-07330KL" 1210 35,66.3 r270 top value=330k
R32 "RC1210FR-07330KL" 1210 35,61.45 r270 top value=330k
R33 "RC1210FR-07330KL" 1210 35,56.6 r270 top value=330k
R34 "RC0603FR-07100RL" 0603#1 34.2,32.7 r270 top value=100
R35 "RC0603FR-075K1L" 0603#1 35.8,32.7 r90 top value=5.10k
R36 "RC0603FR-0751K1L" 0603#1 25.85,62.9 r0 top value=51.1k
R37 "ERJ8BQFR30V" 1206 14.6,65 r270 top value=0.3
R38 "RC1206FR-07430KL" 1206 25.625,50.65 r90 top value=430k
R39 "RC0603FR-0718K7L" 0603#1 25,65.3 r270 top value=18.7k
R40 "RC0603FR-0788K7L" 0603#1 21.039,36.2 r270 top value=88.7k
R41 "RC0603JR-070RL" 0603#1 27,45.3 r270 top value=0
R42 "RC0603FR-0712KL" 0603#1 19.4,36.2 r90 top value=12.0k
R43 "RC0603FR-071KL" 0603#1 35.1,39.8 r180 top value=1.00k
R44 "RC0603FR-075K1L" 0603#1 19.4,45 r90 top value=5.10k
R45 "RC0603FR-072K4L" 0603#1 31.25,46.6 r90 top value=2.40k
R46 "RC0603FR-0710KL" 0603#1 69.5,16 r270 top value=10.0k
R47 "RC0603FR-0710KL" 0603#1 39.5,32.5 r90 top value=10.0k
R48 "RC0603JR-070RL" 0603#1 52,11.2 r180 top value=0
R49 "RC0603JR-070RL" 0603#1 48.7,11.2 r180 top value=0
R50 "RC0603JR-070RL" 0603#1 45.4,11.2 r180 top value=0
R51 "RC0603JR-070RL" 0603#1 42.162,11.2 r180 top value=0
R52 "RC0603JR-070RL" 0603#1 38.9,11.2 r180 top value=0
R53 "RC0603FR-071KL" 0603#1 56.58,7.858 r270 top value=1.00k
R54 "RC0603JR-070RL" 0603#1 35.6,11.2 r180 top value=0
R55 "RC0603FR-0710RL" 0603#1 64.6,16 r270 top value=10.0
R56 "RC0603JR-070RL" 0603#1 22.1,4.2 r180 top value=0
R57 "RC0603FR-0710RL" 0603#1 66.2,16 r270 top value=10.0
R58 "RC0603FR-0710KL" 0603#1 71.8,31.662 r270 top value=10.0k
R59 "RC0603JR-070RL" 0603#1 22.1,6.7 r180 top value=0
R60 "RC0603JR-070RL" 0603#1 22.1,9.22 r180 top value=0
R61 "RC0603FR-07100RL" 0603#1 65.7,31.8 r90 top value=100
R62 "RC0603JR-070RL" 0603#1 22.1,11.8 r180 top value=0
R63 "RC0603FR-071KL" 0603#1 71.5,15.9 r270 top value=1.00k
R64 "RC0603JR-070RL" 0603#1 22.1,14.333 r180 top value=0
R65 "RC0603FR-07100RL" 0603#1 67.4,31.8 r90 top value=100
R66 "RC0603JR-070RL" 0603#1 22.1,16.867 r180 top value=0
R67 "RC0603FR-0710KL" 0603#1 68.978,31.74 r270 top value=10.0k
R68 "RC0603JR-070RL" 0603#1 22.1,19.4 r180 top value=0
R69 "RC0603JR-070RL" 0603#1 22.1,21.933 r180 top value=0
R70 "RC0603FR-07100RL" 0603#1 81.526,16 r90 top value=100
R71 "RC0603JR-070RL" 0603#1 22.1,24.467 r180 top value=0
R72 "RC0603FR-0710KL" 0603#1 90.6,16 r90 top value=10.0k
R73 "RC0603FR-07100RL" 0603#1 83.1,16 r90 top value=100
R74 "RC0603FR-07100RL" 0603#1 22.1,27 r180 top value=100
R75 "RC0603FR-071KL" 0603#1 89,16 r270 top value=1.00k
R76 "RC0603FR-071KL" 0603#1 75.1,16 r90 top value=1.00k
R77 "RC0603FR-072K4L" 0603#1 76.7,16 r90 top value=2.40k
R78 "RC0603FR-071KL" 0603#1 146.6,6.2 r180 top value=1.00k
R79 "RC0603FR-07100RL" 0603#1 130.2,5.6 r0 top value=100
R80 "RC0603FR-071KL" 0603#1 130.2,3.9 r180 top value=1.00k
R81 "RC0603FR-07100RL" 0603#2 141.4,3.2 r90 top value=100
R82 "RC0603JR-070RL" 0603#1 91.8,7.1 r0 top value=0
R83 "RC0603FR-071KL" 0603#1 94.8,16.9 r180 top value=1.00k
R84 "RC0603JR-070RL" 0603#1 99.3,9.2 r0 top value=0
R85 "RC0603JR-070RL" 0603#1 123.5,39.5 r0 top value=0
R86 "RC0603JR-070RL" 0603#1 123.4,37.9 r0 top value=0
R87 "RC0603FR-071K5L" 0603#1 62.3,7.5 r180 top value=1.50k
R88 "RC0603JR-070RL" 0603#1 68.49,10.45 r270 top value=0
RT1 "MS22 50004" MS2250004 72.9,57.3 r270 top value=50
S1 "200AWMSP1T1A1M2QE" FP-200AWMSP1T1A1M2QE_PTH_SW_8MM13_5MM08-MFG 107.34,4.5 r0 top
TP1 "5015" Testpoint_Keystone_Miniature 81.3,64.2 r180 top
TP2 "5015" Testpoint_Keystone_Miniature 12.7,98.3 r180 top
TP3 "5015" Testpoint_Keystone_Miniature 34.9,74.2 r0 top
TP4 "5015" Testpoint_Keystone_Miniature 115.9,18.9 r90 top
TP5 "5015" Testpoint_Keystone_Miniature 121.012,18.8 r90 top
TP6 "5015" Testpoint_Keystone_Miniature 103.9,48.171 r180 top
TP7 "5015" Testpoint_Keystone_Miniature 97.7,48.267 r0 top
TP8 "5015" Testpoint_Keystone_Miniature 2.7,95.8 r180 top
TP9 "5015" Testpoint_Keystone_Miniature 72.6,44.2 r180 top
TP10 "5015" Testpoint_Keystone_Miniature 111.5,18.9 r270 top
TP11 "5015" Testpoint_Keystone_Miniature 108.2,18.9 r270 top
TP12 "5015" Testpoint_Keystone_Miniature 82,40.5 r180 top
TP13 "5015" Testpoint_Keystone_Miniature 109.9,63.5 r0 top
TP14 "5015" Testpoint_Keystone_Miniature 102.9,35.2 r90 top
TP15 "5015" Testpoint_Keystone_Miniature 122.8,26.2 r90 top
TP17 "5015" Testpoint_Keystone_Miniature 86.3,40.5 r0 top
TP18 "5015" Testpoint_Keystone_Miniature 126.4,21.4 r90 top
TP19 "5015" Testpoint_Keystone_Miniature 129.3,14.1 r90 top
TP20 "5015" Testpoint_Keystone_Miniature 32.1,31.2 r270 top
TP21 "5015" Testpoint_Keystone_Miniature 26.15,60.6 r180 top
TP22 "5015" Testpoint_Keystone_Miniature 28.6,42.3 r0 top
TP23 "5015" Testpoint_Keystone_Miniature 33.8,37.5 r0 top
TP25 "5015" Testpoint_Keystone_Miniature 14.1,61.3 r0 top
TP26 "5015" Testpoint_Keystone_Miniature 11.9,43.5 r180 top
TP28 "5015" Testpoint_Keystone_Miniature 128.8,27.4 r90 top
TP29 "5015" Testpoint_Keystone_Miniature 3.7,23.467 r180 top
TP30 "5015" Testpoint_Keystone_Miniature 105.039,9.8 r180 top
TP31 "5015" Testpoint_Keystone_Miniature 150.1,1.4 r0 top
TP32 "5015" Testpoint_Keystone_Miniature 127.2,7.4 r270 top
TP33 "5015" Testpoint_Keystone_Miniature 127.2,2.7 r270 top
TP34 "5015" Testpoint_Keystone_Miniature 145.4,1.5 r0 top
U1 "GaN daughter board" "GAN DAUGHTER BOARD 3" 64.5,18 r180 bottom locked
U2 "TLV9062IDR" D0008A_N 111.6,33.061 r0 top
U3 "AMC3302DWE" DWE0016A-MFG 131.686,35.362 r180 top
U4 "UCC28710DR" D0007A_N 19.993,64.7 r180 top
U5 "TPS54202DDCR" DDC0006A_N 24.037,36.2 r180 top
U6 "TLV74033PDBVR" DBV0005A-MFG 92.4,31.156 r0 top
U7 "ISO6721BDR" D0008A-MFG 136.8,4.7 r0 top
U8 "UCC27624D" D0008A-MFG 88.4,10.8 r0 top

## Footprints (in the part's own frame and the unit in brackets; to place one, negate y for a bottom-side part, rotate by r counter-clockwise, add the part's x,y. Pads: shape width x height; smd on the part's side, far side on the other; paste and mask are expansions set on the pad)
0-MFG [mm]
  body extent -90,-60 90,60, height 27
0603#1 [mm] "0603 from SM-752 data"
  rect 1x0.95 smd: 1(-0.8,0) 2(0.8,0)
  silkscreen extent -1.52,-0.69 1.52,0.69, body extent -0.87,-0.47 0.87,0.47, height 1
0603#2 [mm] "0603 from SM-752 data"
  rect 1x0.95 smd: 1(0.8,0) 2(-0.8,0)
  silkscreen extent -1.52,-0.69 1.52,0.69, body extent -0.87,-0.47 0.87,0.47, height 1
1206 [mm] "1206 from SM-752 data"
  rect 1.3x1.85 smd: 1(-1.45,0) 2(1.45,0)
  silkscreen extent -2.4,-1.21 2.4,1.21, body extent -1.7,-0.9 1.7,0.9, height 1.35
1206_180 [mm] "1206_180"
  rect 1.1x1.6 smd: 1(-1.7,0) 2(1.7,0)
  silkscreen extent -0.9,-1 0.9,1, body extent -1.75,-0.95 1.75,0.95, height 1.8
1210 [mm] "1210 from SM-752 data"
  rect 1.3x2.7 smd: 1(-1.45,0) 2(1.45,0)
  silkscreen extent -2.32,-1.57 2.32,1.57, body extent -1.7,-1.35 1.7,1.35, height 1.35
2512 [mm] "Chip Resistor, Body 6.3x3.2mm, IPC Medium Density"
  rect 1.3x3.4 smd: 1(-2.95,0) 2(2.95,0)
  silkscreen extent -1.9,-1.6 1.9,1.6, body extent -3.22,-1.67 3.22,1.67, height 0.71
ARLDC807842C201N1B [mm]
  round 5 hole 2.5: 1(-0.034,-0.094) 2(0,-39.37)
  silkscreen extent -34,-68.29 34,2.71, body extent -34,-67.5 34,3.5, height 33.14
AY2_1300x500_Straight [mm] "TH, 2-Leads, 11x5mm, Pin Spacing 7.5mm"
  round 1.4 hole 0.9: 1(-3.75,1.6) 2(3.75,-1.6)
  silkscreen extent -6.5,-2.5 6.5,2.5, body extent -6.5,-2.5 6.5,2.5, height 16
B32924_24.5mm [mm] "Epcos film capacitors, 27.5mm spacing"
  rect 1.5x1.5 hole 1: 1(-13.75,0)
  round 1.5 hole 1: 2(13.75,0)
  silkscreen extent -15.75,-7 15.75,7, body extent -15.75,-7 15.75,7, height 24.5
BOOST_INDUCTOR_250UH [mm] "Boost inductor 250uH"
  rect 2.54x2.54 hole 2.007: 1(0,0)
  round 4 hole 3: 2(7.5,0) 6(19,21)
  round 2.54 hole 2.007: 3(19,0) 4(26.5,0) 5(26.5,21) 7(7.5,21) 8(0,21)
  silkscreen extent -18.5,-7.5 43.5,28.5, body extent -21.99,-7.5 45.99,28.1, height 76.4
"Cap_35x60mm_Snap in" [mm] "Electrolytic capacitor 35x60mm snap in"
  rrect20% 7x2 hole 1 slot 6 at 0 deg: 1(-5,-4.2)
  rrect20% 2x7 hole 1 slot 6 at 90 deg: 2(9.2,0)
  silkscreen extent -20.51,-18 18,18, body extent -18,-18 18,18, height 62
controlCARD-120HSEC [mm] "Pads are not numbered according to Samtec datasheet."
  rect 0.5x2.724 smd: 1(-23.357,-1.678) 2(-23.357,1.722) 3(-22.557,-1.678) 4(-22.557,1.722) 5(-21.757,-1.678) 6(-21.757,1.722) 7(-20.957,-1.678) 8(-20.957,1.722) 9(-20.157,-1.678) 10(-20.157,1.722) 11(-19.357,-1.678) 12(-19.357,1.722) 13(-18.557,-1.678) 14(-18.557,1.722) 15(-17.757,-1.678) 16(-17.757,1.722) 17(-16.957,-1.678) 18(-16.957,1.722) 19(-16.157,-1.678) 20(-16.157,1.722) 21(-15.357,-1.678) 22(-15.357,1.722) 23(-14.557,-1.678) 24(-14.557,1.722) 25(-13.757,-1.678) 26(-13.757,1.722) 27(-12.957,-1.678) 28(-12.957,1.722) 29(-12.157,-1.678) 30(-12.157,1.722) 31(-11.357,-1.678) 32(-11.357,1.722) 33(-10.557,-1.678) 34(-10.557,1.722) 35(-9.757,-1.678) 36(-9.757,1.722) 37(-8.957,-1.678) 38(-8.957,1.722) 39(-8.157,-1.678) 40(-8.157,1.722) 41(-7.357,-1.678) 42(-7.357,1.722) 43(-6.557,-1.678) 44(-6.557,1.722) 45(-5.757,-1.678) 46(-5.757,1.722) 47(-4.957,-1.678) 48(-4.957,1.722) 49(-4.157,-1.678) 50(-4.157,1.722) 51(-3.357,-1.678) 52(-3.357,1.722) 53(-2.557,-1.678) 54(-2.557,1.722) 55(-1.757,-1.678) 56(-1.757,1.722) 57(2.243,-1.678) 58(2.243,1.722) 59(3.043,-1.678) 60(3.043,1.722) 61(3.843,-1.678) 62(3.843,1.722) 63(4.643,-1.678) 64(4.643,1.722) 65(5.443,-1.678) 66(5.443,1.722) 67(6.243,-1.678) 68(6.243,1.722) 69(7.043,-1.678) 70(7.043,1.722) 71(7.843,-1.678) 72(7.843,1.722) 73(8.643,-1.678) 74(8.643,1.722) 75(9.443,-1.678) 76(9.443,1.722) 77(10.243,-1.678) 78(10.243,1.722) 79(11.043,-1.678) 80(11.043,1.722) 81(11.843,-1.678) 82(11.843,1.722) 83(12.643,-1.678) 84(12.643,1.722) 85(13.443,-1.678) 86(13.443,1.722) 87(14.243,-1.678) 88(14.243,1.722) 89(15.043,-1.678) 90(15.043,1.722) 91(15.843,-1.678) 92(15.843,1.722) 93(16.643,-1.678) 94(16.643,1.722) 95(17.443,-1.678) 96(17.443,1.722) 97(18.243,-1.678) 98(18.243,1.722) 99(19.043,-1.678) 100(19.043,1.722) 101(19.843,-1.678) 102(19.843,1.722) 103(20.643,-1.678) 104(20.643,1.722) 105(21.443,-1.678) 106(21.443,1.722) 107(22.243,-1.678) 108(22.243,1.722) 109(23.043,-1.678) 110(23.043,1.722) 111(23.843,-1.678) 112(23.843,1.722) 113(24.643,-1.678) 114(24.643,1.722) 115(25.443,-1.678) 116(25.443,1.722) 117(26.243,-1.678) 118(26.243,1.722) 119(27.043,-1.678) 120(27.043,1.722)
  round 0.025 hole 1.27 unplated mask+0.876: 181(-24.857,0.022) 182(28.543,1.522)
  round 1.348 hole 0.84: 185(-27.207,0.022) 186(30.893,0.022)
  silkscreen extent -32.11,-3.86 35.8,3.9, body extent -31.75,-3.48 35.3,3.52, height 12.35
D0007A_N [mm] "SOIC, 7-Leads, Body 4.9x3.9mm, Pitch 1.27mm, IPC Medium Density"
  oval 1.45x0.6 smd: 1(-2.725,1.905) 2(-2.725,0.635) 3(-2.725,-0.635) 4(-2.725,-1.905) 5(2.725,-1.905) 6(2.725,-0.635) 8(2.725,1.905)
  silkscreen extent -3.33,-2.5 1.1,2.52, body extent -3.01,-2.45 3.01,2.45, height 1.75
D0008A-MFG [mm]
  rrect17% 1.55x0.6 smd paste+0 mask+0: 1(-2.7,1.905) 2(-2.7,0.635) 3(-2.7,-0.635) 4(-2.7,-1.905) 5(2.7,-1.905) 6(2.7,-0.635) 7(2.7,0.635) 8(2.7,1.905)
  silkscreen extent -4.17,-2.5 1.5,2.5, body extent -3.57,-2.75 3.57,2.75, height 0.25
D0008A_N [mm] "SOIC, 8-Leads, Body 4.9x3.9mm, Pitch 1.27mm, IPC Medium Density"
  oval 1.45x0.6 smd: 1(-2.725,1.905) 2(-2.725,0.635) 3(-2.725,-0.635) 4(-2.725,-1.905) 5(2.725,-1.905) 6(2.725,-0.635) 7(2.725,0.635) 8(2.725,1.905)
  silkscreen extent -3.3,-2.5 0.9,2.5, body extent -3,-2.45 3,2.45, height 1.63
DBV0005A-MFG [mm]
  rrect17% 1.1x0.6 smd paste+0 mask+0: 1(-1.3,0.95) 2(-1.3,0) 3(-1.3,-0.95) 4(1.3,-0.95) 5(1.3,0.95)
  silkscreen extent -2.57,-1.53 0.88,1.53, body extent -1.95,-1.78 1.95,1.78, height 0.25
DDC0006A_N [mm]
  rrect17% 1x0.6 smd: 1(-1.375,0.95) 2(-1.375,0) 3(-1.375,-0.95) 4(1.375,-0.95) 5(1.375,0) 6(1.375,0.95)
  silkscreen extent -1.75,-1.52 0.7,1.52, body extent -1.43,-1.48 1.43,1.49, height 0.92
DIODE_BRIDGE_HORIZONTAL_GBJ [mm] "diode bridge horizontal GBJ"
  rect 2.3x2.3 hole 1.6: 1(0,0)
  round 2.3 hole 1.6: 2(-10,0) 3(-17.5,0) 4(-25,0)
  round 8 hole 8 unplated: ""(-12.5,19.5)
  silkscreen extent -27.5,1.5 2.5,28.5, body extent -27.5,1.5 2.5,28.5, height 11.05
DPAK [mm] "D-PAK, 3-Pads, Body 6.22x6.73mm (max), TO-252AA using nominal STEP model"
  rrect6% 2.6x1.6 smd: 1(-3.4,2.28) 3(-3.4,-2.28)
  rrect2% 6.2x5.8 smd paste-3: 2(3.4,0)
  body extent -3.86,-3.29 5.84,3.29, height 2.48
DWE0016A-MFG [mm]
  rrect17% 1.65x0.6 smd paste+0 mask+0: 1(-4.875,4.445) 2(-4.875,3.175) 3(-4.875,1.905) 4(-4.875,0.635) 5(-4.875,-0.635) 6(-4.875,-1.905) 7(-4.875,-3.175) 8(-4.875,-4.445) 9(4.875,-4.445) 10(4.875,-3.175) 11(4.875,-1.905) 12(4.875,-0.635) 13(4.875,0.635) 14(4.875,1.905) 15(4.875,3.175) 16(4.875,4.445)
  silkscreen extent -6.38,-5.25 3.5,5.25, body extent -5.8,-5.5 5.8,5.5, height 0.25
FCC_disclaimer_stacked [mm]
Fiducial10-20 [mm]
  round 1 smd mask+0.5: 1(0,0)
  Top Layer keep-out circle w1.178: c0,0 r0.5
FP-1-2834011-2_HDR2-MFG [mm]
  rrect5% 2x2 hole 1.3 paste-1000 mask+0: 1(-0.85,3.8)
  round 2 hole 1.3 paste-1000 mask+0: 2(2.65,-1.4)
  silkscreen extent -4.5,-6.15 4.5,6.72, body extent -4.6,-6.25 4.6,6.25, height 0.25
FP-200AWMSP1T1A1M2QE_PTH_SW_8MM13_5MM08-MFG [mm]
  rrect6% 1.69x1.69 hole 1.09 paste-1000 mask+0: 1(-2.54,0)
  oval 2x3 hole 1.5 slot 2.5 at 90 deg paste-1000 mask+0.1: 2(0,0)
  round 1.69 hole 1.09 paste-1000 mask+0: 3(2.54,0)
  silkscreen extent -4.75,-2.67 4.19,2.67, body extent -4.29,-2.77 4.29,2.77, height 0.25
FP-63824-1_CONN_7MM92_3MM11-MFG [mm]
  round 2.15 hole 1.4 paste-1000 mask+0: 1(-2.54,0) 1(2.54,0)
  silkscreen extent -4.09,-1.56 4.09,1.56, body extent -3.96,-1.54 3.96,1.54, height 10.88
FP-0525025.MXEP_vm_AXIAL-MFG [mm]
  rrect5% 2.15x2.15 hole 1.4 paste-1000 mask+0: 1(0,0)
  round 2.15 hole 1.4 paste-1000 mask+0: 2(8.093,0)
  silkscreen extent -3.64,-3.64 3.64,3.64, body extent -3.74,-3.74 9.27,3.74, height 0.25
FP-890334027012CS_RADIAL-MFG [mm]
  rrect6% 1.7x1.7 hole 1.1 paste-1000 mask+0: 1(-13.75,0)
  round 1.7 hole 1.1 paste-1000 mask+0: 2(13.75,0)
  silkscreen extent -15.75,-6.75 15.75,6.75, body extent -15.85,-6.85 15.85,6.85, height 0.25
FP-S861021486045_RADIAL-MFG [mm]
  rrect3% 3.05x3.05 hole 2 paste-1000 mask+0: 1(-5,0)
  round 3.05 hole 2 paste-1000 mask+0: 2(5,0)
  silkscreen extent -18,-18 18,18, body extent -18.1,-18.1 18.1,18.1, height 0.25
FP-SSM-107-L-SV-BE_HDR7-MFG [mm]
  rrect10% 1.02x1.905 smd paste+0 mask+0: 1(-7.62,-1.603) 2(-5.08,1.603) 3(-2.54,-1.603) 4(0,1.603) 5(2.54,-1.603) 6(5.08,1.603) 7(7.62,-1.603)
  round 1.02 hole 1.02 unplated paste-1000 mask+0: ""(-7.62,0) ""(-5.08,0) ""(-2.54,0) ""(0,0) ""(2.54,0) ""(5.08,0) ""(7.62,0)
  silkscreen extent -9.02,-3.27 9.02,1.34, body extent -9.12,-2.66 9.12,2.66, height 0.25
FP-UCY2W150MPD1TD_RADIAL-MFG [mm]
  rrect8% 1.25x1.25 hole 0.75 paste-1000 mask+0: 1(-2.5,0)
  round 1.25 hole 0.75 paste-1000 mask+0: 2(2.5,0)
  silkscreen extent -5.25,-5.25 5.25,5.25, body extent -5.35,-5.35 5.35,5.35, height 0.25
"GAN DAUGHTER BOARD 3" [mm]
  round 7.4 hole 4.4 paste-1000: 1(-18,39) 2(-30,39) 3(-42,39)
  silkscreen extent -68.1,6.9 0.1,40.1, body extent -68,0 0,45, height 9.19
HV_800x1500 [mm] "Based on Nichicon HV series"
  rect 1.35x1.35 hole 0.85: 1(-1.75,0)
  round 1.35 hole 0.85: 2(1.75,0)
  silkscreen extent -4.25,-4.25 4.25,4.25, body extent -4.22,-4.24 4.24,4.24, height 16.51
IEC_HighVoltage_Small [mm]
  silkscreen extent -2.72,-2.24 2.72,2.47
IEC_HotSurface_Small [mm]
  silkscreen extent -2.72,-2.36 2.72,2.35
JST_B2B-XH-A [mm] "Header (Shrouded), 2.5mm, 2x1, TH"
  rect 1.5x1.5 hole 1: 1(-1.25,0)
  round 1.5 hole 1: 2(1.25,0)
  silkscreen extent -4,-3.37 3.7,2.38, body extent -3.7,-3.37 3.7,2.38, height 7
Keystone29311 [mm] "Srcew, Pan HeadM5x0.5 mm, Zinc Plated  6.0mm L"
  round 7 / inner round 4.9 / far side round 7 hole 3.7: 1(0,0)
  body extent -2.7,-2.7 2.7,2.7, height 1.72
KY_700x500x1000 [mm] "TH, 2- Leads, Body 7x5mm, Pin Spacing 7.5mm"
  round 1.4 hole 0.9: 1(-3.75,0) 2(3.75,0)
  silkscreen extent -3.5,-2.5 3.5,2.5, body extent -4.05,-2.5 4.05,2.5, height 9.97
KY_1000x500x1300 [mm] "MuRata"
  round 1.5 hole 0.9: 1(-3.75,0) 2(3.75,0)
  silkscreen extent -5,-2.5 5,2.5, body extent -5,-2.5 5,2.5, height 13
Label_650x200 [mil] "Thermal Transfer Label"
  round 1 on Mech13: 0(0,0)
  silkscreen extent -325,-100 325,100, body extent -325,-100 325,100, height 1
LTST-C193_Green [mm] "SMD, 2-Leads, Body1.6x0.8mm"
  rect 0.8x0.8 smd: 1(-0.75,0) 2(0.75,0)
  silkscreen extent -1.2,-0.9 1.85,0.9, body extent -0.85,-0.45 0.85,0.45, height 0.45
LTST-C193_Red [mm] "SMD, 2-Leads, Body1.6x0.8mm"
  rect 0.8x0.8 smd: 1(-0.75,0) 2(0.75,0)
  silkscreen extent -1.2,-0.9 1.85,0.9, body extent -0.85,-0.45 0.85,0.45, height 0.45
MS2250004 [mm] "INRSH CURR LIMITER 50 OHM 25% 4A 23MM"
  round 2 hole 1.2: 1(3.35,-3.4) 2(-3.35,3.4)
  silkscreen extent -11.5,-5 11.5,5, body extent -11.81,-3.81 11.81,3.81, height 27.3
"NY PMS 440 0025 PH" [mm] "4-40 nylon screw and mounting hole"
  round 8 hole 3.2: 1(0,0)
  body extent -3.3,-3.3 3.3,3.3, height 2.69
PW_500x700 [mm] "Nichicon"
  rect 1.25x1.25 hole 0.711: 1(-1,0)
  round 1.25 hole 0.711: 2(1,0)
  silkscreen extent -2.8,-2.8 2.8,2.8, body extent -2.73,-2.75 2.75,2.75, height 8.01
Relay_T9AS1D12 [mm] "TH, 4-Leads, Body 32.51x27.43mm"
  rect 2.5x2.5 hole 1.98: 1(-8.89,5.08)
  round 2.6 hole 2.06: 2(8.89,7.62)
  round 1.6 hole 1.09: 3(-5.08,-7.62) 4(5.08,-7.62)
  silkscreen extent -13.79,-14.73 14.15,17.79, body extent -13.26,-14.73 14.17,17.78, height 20.45
Samtec_TSS-110-02-G-D [mm] "Header, 2.54mm, 10x2, TH"
  rrect50% 1.53x1.53 hole 1.02: 1(-1.27,11.43)
  round 1.53 hole 1.02: 2(1.27,11.43)
  round 1.53 hole 1.02 mask+0.102: 3(-1.27,8.89) 4(1.27,8.89) 5(-1.27,6.35) 6(1.27,6.35) 7(-1.27,3.81) 8(1.27,3.81) 9(-1.27,1.27) 10(1.27,1.27) 11(-1.27,-1.27) 12(1.27,-1.27) 13(-1.27,-3.81) 14(1.27,-3.81) 15(-1.27,-6.35) 16(1.27,-6.35) 17(-1.27,-8.89) 18(1.27,-8.89) 19(-1.27,-11.43) 20(1.27,-11.43)
  body extent -4.45,-14.6 4.83,14.6, height 8.89
SMA [mm] "Molded Diode, 2-Leads, Body 4.3x2.6mm, IPC Medium Density, based on OnSemi component dimensions and land pattern"
  rect 2x2 smd: 1(-2,0) 2(2,0)
  silkscreen extent -3.66,-1.57 2.79,1.57, body extent -2.6,-1.3 2.6,1.3, height 2.42
SMC [mil] "Molded Diode, 2-Leads, Body 6.9x5.8mm, IPC Medium Density, based on OnSemi component dimensions and land patterns"
  rect 110x150 smd: 1(-140.49,0) 2(140.49,0)
  silkscreen extent -221,-123 189,124, body extent -156,-116 156,116, height 91
SOD-123 [mm] "On Semi recommended land pattern"
  rect 0.915x1.22 smd: 1(-1.637,0) 2(1.637,0)
  silkscreen extent -2.74,-1.17 2.03,1.17, body extent -1.93,-0.9 1.93,0.9, height 1.35
SOT-23 [mm] "SOT23, 3-Leads, Body 2.9x1.3mm, Pitch 0.95mm, Lead Span 2.5mm, IPC Medium Density"
  rrect50% 1x0.6 smd: 1(-1.2,0.95) 2(-1.2,-0.95) 3(1.2,0)
  silkscreen extent -1.62,-1.5 0.7,1.5, body extent -1.16,-1.45 1.21,1.45, height 1
TE_644695-4 [mm] "Header, 2.54 mm, 4x1, TH"
  rect 1.5x1.5 hole 1: 1(-3.81,0)
  round 1.5 hole 1: 2(-1.27,0) 3(1.27,0) 4(3.81,0)
  silkscreen extent -4.93,-1.17 4.93,1.74, body extent -4.98,-1.17 4.88,1.17, height 10.29
Testpoint_Keystone_Miniature [mil] "Miniature SMT test point"
  rect 135x70 smd: 1(0,0)
  silkscreen extent -78,-46 78,45, body extent -52,-20 52,20, height 61
TI_Stacked_Overlay_Small [mm]
  silkscreen extent -10.63,-2.49 10.63,2.49
UVY_1000x1250 [mm] "Capacitor, Electrolytic, Radial; Body 10 x 12.5 mm (Dia.xH typ); Pin Spacing 5 mm (typ)"
  rect 1.4x1.4 hole 0.889: 1(-2.5,0)
  round 1.4 hole 0.889: 2(2.5,0)
  silkscreen extent -5.28,-5.27 5.22,5.22, body extent -5,-5 5,5, height 14.12
WE-PD_1280 [mm] "Wurth Elektronik recommended land pattern"
  rect 2.9x5.4 smd: 1(-4.95,0) 2(4.95,0)
  silkscreen extent -6,-6 6,6, body extent -6,-6 6,6, height 8.01
WE-TI_5075 [mm] "Wurth WE-TI 5075"
  rect 1.4x1.4 hole 0.787: 1(-1.25,0)
  round 1.4 hole 0.787: 2(1.25,0)
  silkscreen extent -3,-3 3,3, body extent -3,-3 3,3, height 8.5
WE_LQS_252012 [mm] "SMD, 2-Leads, Body 2.5x2mm, Pitch 1.9mm"
  rect 1.1x2 smd: 1(-0.95,0) 2(0.95,0)
  silkscreen extent -0.1,-1 0.1,1, body extent -1.25,-1 1.25,1, height 1.2
WEEE_Minimum [mm] "WEEElie bin"
  silkscreen extent -2.42,-4.38 2.52,2.65
Wurth_971120321 [mm] "HEX STANDOFF M3 STEEL 12MM"
  body extent -3.18,-2.75 3.18,2.75, height 18
Wurth_694106301002 [mm] "WR-DC DC Power Jack, R/A, TH"
  rect 3.5x1.3 hole 0.8 slot 3 at 0 deg: 1(0,-2.9) 2(0,2.9)
  rect 1.3x3.5 hole 0.8 slot 3 at 90 deg: 3(-4.8,0.1)
  silkscreen extent -4.5,-3.8 4.9,10.7, body extent -4.9,-3.8 4.5,10.7, height 10.63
